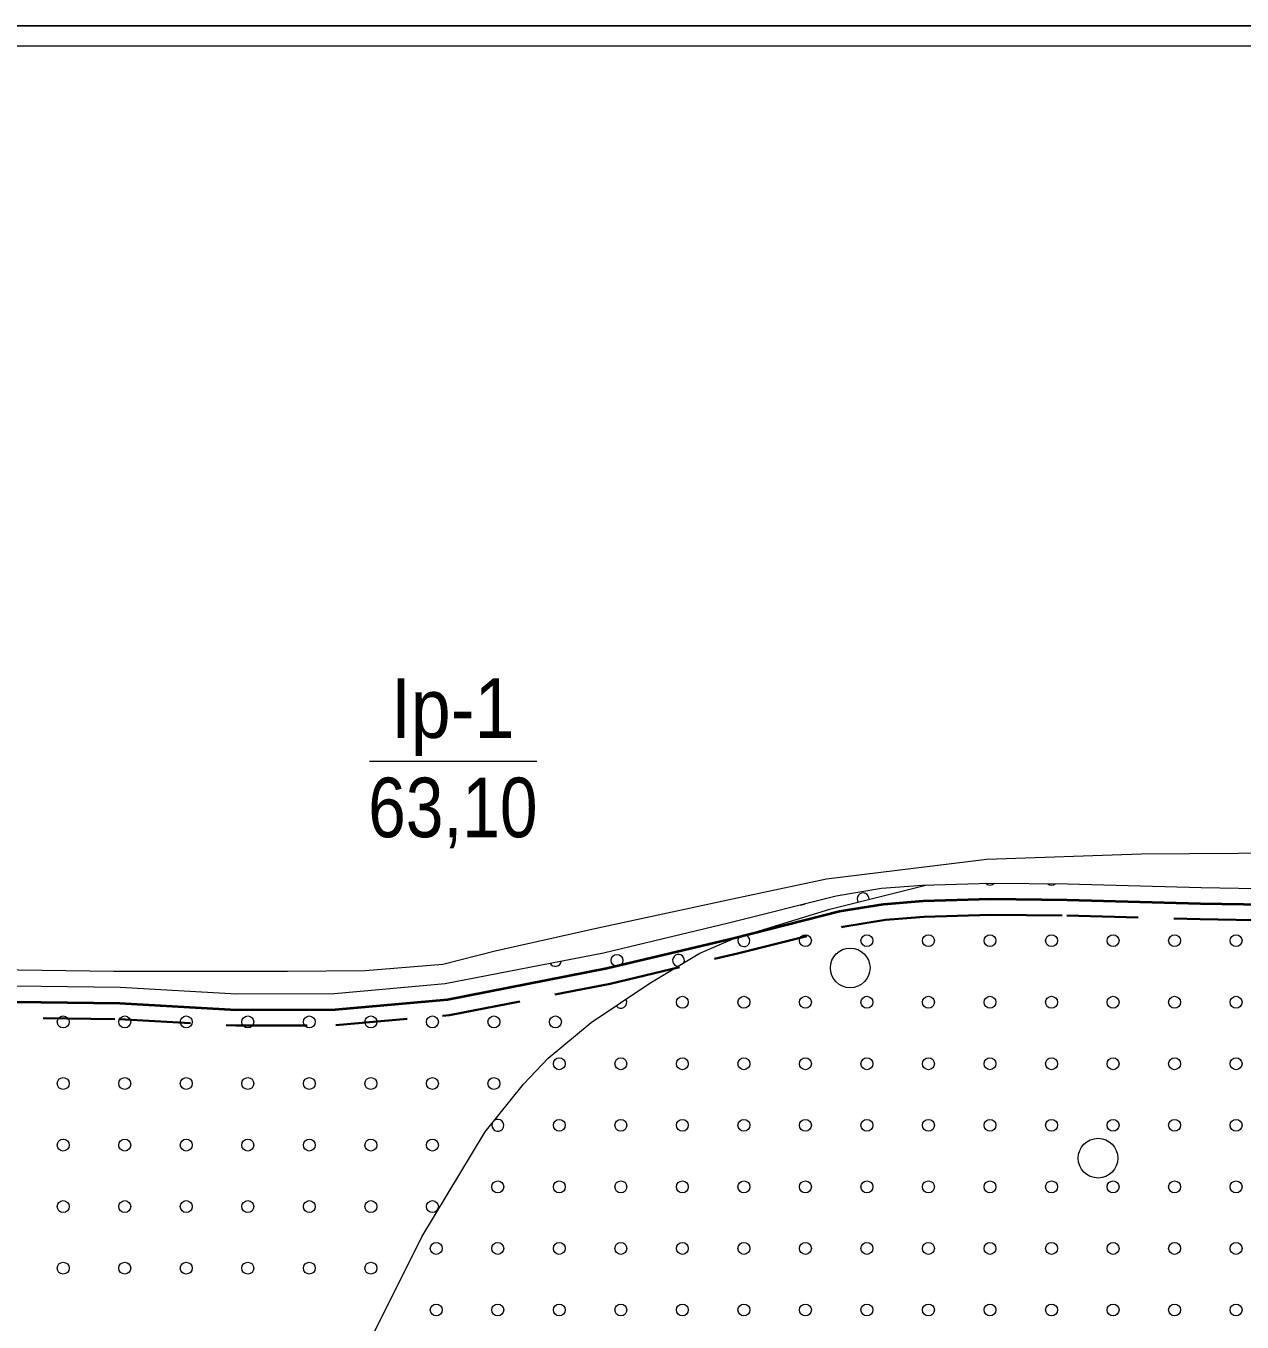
# Model space of a CAD drawing. Extents: x 640121 to 640955, y 6441885 to 6442246.
# Drawn here: x 640243.1 to 640304.3, y 6442180.9 to 6442246.2 of the extents above; entities that cross this region are included whole.
import ezdxf
from ezdxf.enums import TextEntityAlignment as Align

# ---------------------------------------------------------------- set-up
doc = ezdxf.new("R2010")
doc.units = 0
doc.header["$LTSCALE"] = 1.2
doc.linetypes.add('MEDIUM_DASHED', pattern=[4.5, 3, -1.5])
for name, color, linetype, lineweight in [('31', 7, 'Continuous', 13), ('32', 7, 'Continuous', 13), ('35', 7, 'Continuous', 35), ('43', 7, 'Continuous', 13), ('47', 7, 'Continuous', 13), ('50', 7, 'Continuous', 13)]:
    doc.layers.add(name, color=color, linetype=linetype, lineweight=lineweight)

msp = doc.modelspace()

# ---------------------------------------------------------------- linework, layer by layer
at = {"layer": '31'}
for points in [[(640237.88, 6442198.68), (640247.48, 6442198.55), (640256.25, 6442198.56), (640260.16, 6442198.58), (640264.07, 6442198.91), (640266.7, 6442199.57), (640271.88, 6442200.73), (640278.66, 6442202.2), (640283.4, 6442203.21), (640291.48, 6442204.19), (640299.25, 6442204.46), (640306.57, 6442204.52), (640314.94, 6442205.13), (640322.95, 6442205.69), (640332.32, 6442206.21), (640341.15, 6442206.58), (640352.14, 6442207.08), (640362.7, 6442207.53), (640371.1, 6442207.66)], [(640238.51, 6442197.86), (640247.81, 6442197.74), (640253.68, 6442197.41), (640258.61, 6442197.43), (640264.19, 6442197.93), (640272.16, 6442199.48), (640278.53, 6442201), (640283.89, 6442202.35), (640286.18, 6442202.73), (640288.23, 6442202.89), (640291.66, 6442202.99), (640295.54, 6442202.95), (640302.27, 6442202.77), (640309.83, 6442202.64), (640319.81, 6442202.27), (640328, 6442202.02), (640335.69, 6442202.52), (640340.92, 6442202.71), (640347.43, 6442203.26), (640354.13, 6442203.44), (640362.55, 6442203.68), (640369.1, 6442203.88)], [(640222.36, 6442091.67), (640226.75, 6442095.51), (640231.91, 6442103.63), (640234.2, 6442108.11), (640235.67, 6442111.37), (640238.61, 6442118.45), (640241.77, 6442127.76), (640244.82, 6442137.43), (640247.07, 6442145.34), (640249.45, 6442151.75), (640254.26, 6442165.04), (640257.15, 6442172.33), (640260.17, 6442179.49), (640263.02, 6442185.17), (640266.2, 6442190.46), (640268.13, 6442192.87), (640269.38, 6442194.18), (640271.54, 6442195.96), (640274.5, 6442197.95), (640277.02, 6442199.46), (640278.7, 6442200.19), (640283.57, 6442201.67), (640288.47, 6442202.9)]]:
    msp.add_lwpolyline(points, dxfattribs=at)
at = {"layer": '32'}
msp.add_line((640260.37, 6442209.13), (640268.8, 6442209.13), dxfattribs=at)
at = {"layer": '35', "lineweight": 40}
msp.add_lwpolyline([(640238.53, 6442197.06), (640247.79, 6442196.94), (640253.66, 6442196.61), (640258.64, 6442196.63), (640264.3, 6442197.13), (640272.33, 6442198.7), (640278.72, 6442200.22), (640284.05, 6442201.57), (640286.28, 6442201.93), (640288.27, 6442202.09), (640291.67, 6442202.19), (640295.52, 6442202.15), (640302.25, 6442201.97), (640309.81, 6442201.84), (640319.79, 6442201.47), (640328.01, 6442201.22), (640335.73, 6442201.72), (640340.97, 6442201.91), (640347.48, 6442202.46), (640354.15, 6442202.64), (640362.57, 6442202.88), (640369.12, 6442203.08)], dxfattribs=at)
at = {"layer": '35', "linetype": 'MEDIUM_DASHED'}
msp.add_lwpolyline([(640238.54, 6442196.26), (640247.76, 6442196.14), (640253.64, 6442195.81), (640258.68, 6442195.83), (640264.41, 6442196.34), (640272.5, 6442197.92), (640278.91, 6442199.45), (640284.22, 6442200.78), (640286.37, 6442201.14), (640288.32, 6442201.29), (640291.68, 6442201.39), (640295.51, 6442201.35), (640302.23, 6442201.17), (640309.79, 6442201.04), (640319.76, 6442200.67), (640328.03, 6442200.42), (640335.77, 6442200.92), (640341.02, 6442201.12), (640347.52, 6442201.66), (640354.17, 6442201.84), (640362.6, 6442202.08), (640369.14, 6442202.28)], dxfattribs=at)
at = {"layer": '43'}
for centre in [(640282.338, 6442200.09), (640285.438, 6442200.09), (640288.538, 6442200.09), (640291.638, 6442200.09), (640294.738, 6442200.09), (640297.838, 6442200.09), (640300.938, 6442200.09), (640304.038, 6442200.09), (640272.844, 6442199.096), (640276.138, 6442196.99), (640279.238, 6442196.99), (640282.338, 6442196.99), (640285.438, 6442196.99), (640288.538, 6442196.99), (640291.638, 6442196.99), (640294.738, 6442196.99), (640297.838, 6442196.99), (640300.938, 6442196.99), (640304.038, 6442196.99), (640244.944, 6442195.996), (640248.044, 6442195.996), (640251.144, 6442195.996), (640254.244, 6442195.996), (640257.344, 6442195.996), (640260.444, 6442195.996), (640263.544, 6442195.996), (640266.644, 6442195.996), (640269.744, 6442195.996), (640269.938, 6442193.89), (640273.038, 6442193.89), (640276.138, 6442193.89), (640279.238, 6442193.89), (640282.338, 6442193.89), (640285.438, 6442193.89), (640288.538, 6442193.89), (640291.638, 6442193.89), (640294.738, 6442193.89), (640297.838, 6442193.89), (640300.938, 6442193.89), (640304.038, 6442193.89), (640244.944, 6442192.896), (640248.044, 6442192.896), (640251.144, 6442192.896), (640254.244, 6442192.896), (640257.344, 6442192.896), (640260.444, 6442192.896), (640263.544, 6442192.896), (640266.644, 6442192.896), (640269.938, 6442190.79), (640273.038, 6442190.79), (640276.138, 6442190.79), (640279.238, 6442190.79), (640282.338, 6442190.79), (640285.438, 6442190.79), (640288.538, 6442190.79), (640291.638, 6442190.79), (640294.738, 6442190.79), (640297.838, 6442190.79), (640300.938, 6442190.79), (640304.038, 6442190.79), (640244.944, 6442189.796), (640248.044, 6442189.796), (640251.144, 6442189.796), (640254.244, 6442189.796), (640257.344, 6442189.796), (640260.444, 6442189.796), (640263.544, 6442189.796), (640266.838, 6442187.69), (640269.938, 6442187.69), (640273.038, 6442187.69), (640276.138, 6442187.69), (640279.238, 6442187.69), (640282.338, 6442187.69), (640285.438, 6442187.69), (640288.538, 6442187.69), (640291.638, 6442187.69), (640294.738, 6442187.69), (640297.838, 6442187.69), (640300.938, 6442187.69), (640304.038, 6442187.69), (640244.944, 6442186.696), (640248.044, 6442186.696), (640251.144, 6442186.696), (640254.244, 6442186.696), (640257.344, 6442186.696), (640260.444, 6442186.696), (640263.544, 6442186.696), (640263.738, 6442184.59), (640266.838, 6442184.59), (640269.938, 6442184.59), (640273.038, 6442184.59), (640276.138, 6442184.59), (640279.238, 6442184.59), (640282.338, 6442184.59), (640285.438, 6442184.59), (640288.538, 6442184.59), (640291.638, 6442184.59), (640294.738, 6442184.59), (640297.838, 6442184.59), (640300.938, 6442184.59), (640304.038, 6442184.59), (640244.944, 6442183.596), (640248.044, 6442183.596), (640251.144, 6442183.596), (640254.244, 6442183.596), (640257.344, 6442183.596), (640260.444, 6442183.596), (640263.738, 6442181.49), (640266.838, 6442181.49), (640269.938, 6442181.49), (640273.038, 6442181.49), (640276.138, 6442181.49), (640279.238, 6442181.49), (640282.338, 6442181.49), (640285.438, 6442181.49), (640288.538, 6442181.49), (640291.638, 6442181.49), (640294.738, 6442181.49), (640297.838, 6442181.49), (640300.938, 6442181.49), (640304.038, 6442181.49)]:
    msp.add_circle(centre, 0.3, dxfattribs=at)
for centre, start, end in [((640291.638, 6442203.19), 222.67745, 318.64451), ((640294.738, 6442203.19), 229.99133, 308.66004), ((640285.244, 6442202.196), 353.68577, 214.47819), ((640288.538, 6442203.19), 257.61188, 285.87694), ((640282.144, 6442202.196), 261.36304, 306.91057), ((640279.238, 6442200.09), 139.88896, 73.87214), ((640269.744, 6442199.096), 207.43174, 354.62297), ((640275.944, 6442199.096), 336.587, 265.07933), ((640273.038, 6442196.99), 217.32361, 30.42627), ((640266.838, 6442190.79), 155.55883, 126.88677)]:
    msp.add_arc(centre, 0.3, start, end, dxfattribs=at)
at = {"layer": '47'}
for centre in [(640284.594, 6442198.718), (640297.08, 6442189.135)]:
    msp.add_circle(centre, 1, dxfattribs=at)
at = {"layer": '50', "lineweight": 25}
msp.add_lwpolyline([(640121.33, 6442246.16), (640955.23, 6442246.16), (640955.23, 6441889.4), (640121.33, 6441889.4)], close=True, dxfattribs=at)
at = {"layer": '50'}
msp.add_lwpolyline([(640122.33, 6442245.16), (640954.23, 6442245.16), (640954.23, 6441890.4), (640122.33, 6441890.4)], close=True, dxfattribs=at)

# ---------------------------------------------------------------- texts
at = {"layer": '32'}
for s, width, p in [('Ip-1', 0.9, (640264.565, 6442210.3)), ('63,10', 0.85, (640264.575, 6442205.3))]:
    msp.add_text(s, height=3, dxfattribs=dict(at, width=width)).set_placement(p, align=Align.CENTER)

doc.saveas('drawing.dxf')
